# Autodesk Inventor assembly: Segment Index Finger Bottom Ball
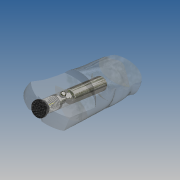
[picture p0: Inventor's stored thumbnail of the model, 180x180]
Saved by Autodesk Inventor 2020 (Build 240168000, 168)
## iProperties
Created: 2019-10
Part Number: Segment Index Finger Bottom Ball
Document SubType Name: Assembly
Designer: yello
Author: yello
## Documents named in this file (6)
- C:\Users\yello\Documents\Mechanical Hand\Prototype 2 (Realistic Hand)\Segment Index Finger Bottom Ball.iam
- C:\Users\yello\Documents\Mechanical Hand\Prototype 2 (Realistic Hand)\Segment Index Finger Bottom.ipt
- C:\Users\yello\Documents\Mechanical Hand\Prototype 2 (Realistic Hand)\Push Part.ipt
- C:\Users\yello\Documents\Mechanical Hand\Prototype 2 (Realistic Hand)\Plug.ipt
- C:\Users\yello\Documents\Mechanical Hand\Prototype 2 (Realistic Hand)\Spring.ipt
- C:\Users\yello\Documents\Mechanical Hand\Prototype 2 (Realistic Hand)\Ball.ipt
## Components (6 placed, 5 different names)
1. Segment Index Finger Bottom:1 — Mate:1, Mate:2, Mate:3, Mate:5, Mate:6, Mate:7
2. Push Part:1 — Mate:1
3. Plug:1 — Mate:2, Mate:3
4. Spring:1 — Mate:5
5. Ball:1 — Mate:6
6. Ball:2 — Mate:7
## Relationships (6: Mate 6)
- Mate:1: Segment Index Finger Bottom:1 ↔ Push Part:1
- Mate:2: Segment Index Finger Bottom:1 ↔ Plug:1
- Mate:3: Segment Index Finger Bottom:1 ↔ Plug:1
- Mate:5: Segment Index Finger Bottom:1 ↔ Spring:1
- Mate:6: Segment Index Finger Bottom:1 ↔ Ball:1
- Mate:7: Segment Index Finger Bottom:1 ↔ Ball:2
